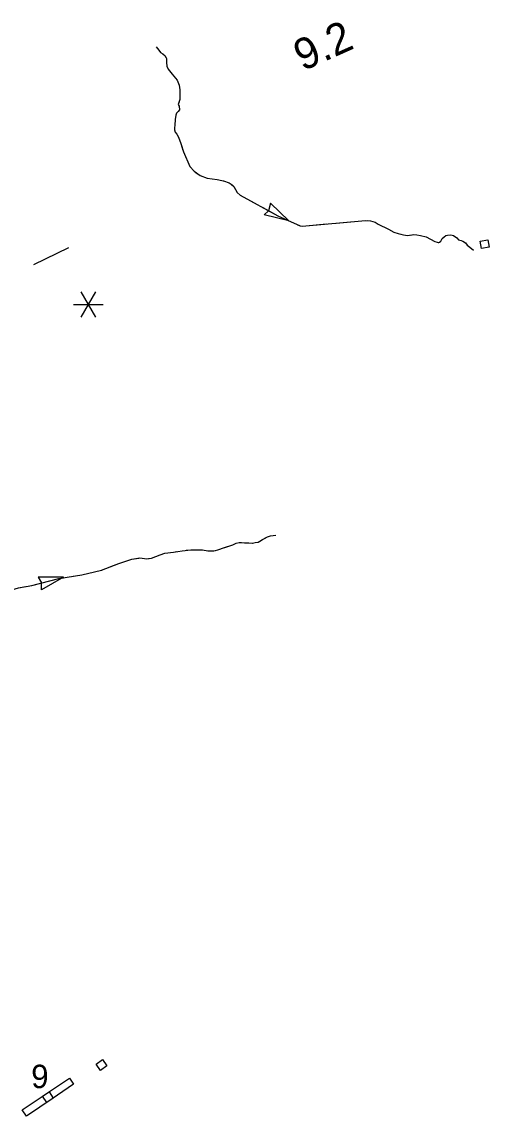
# Model space of a CAD drawing. Extents: x -160 to 6143532, y -375 to 762199.
# Drawn here: x -87.11 to -74.02, y -269.5 to -238.84 of the extents above; entities that cross this region are included whole.
import ezdxf

# ---------------------------------------------------------------- set-up
doc = ezdxf.new("R2010")
doc.units = 0
for name, color, linetype in [('Level 43', 7, 'Continuous'), ('Level 48', 7, 'Continuous'), ('Level 56', 7, 'Continuous')]:
    doc.layers.add(name, color=color, linetype=linetype)

msp = doc.modelspace()

# ---------------------------------------------------------------- linework, layer by layer
at = {"layer": 'Level 43'}
for p, q in [((-80.144, -243.926), (-80.2, -244.136)), ((-79.632, -244.418), (-80.144, -243.926)), ((-80.322, -244.248), (-80.2, -244.136)), ((-79.632, -244.418), (-80.322, -244.248)), ((-85.945, -254.403), (-86.655, -254.4)), ((-86.655, -254.4), (-86.561, -254.564)), ((-85.945, -254.403), (-86.561, -254.755)), ((-86.561, -254.755), (-86.56, -254.566))]:
    msp.add_line(p, q, dxfattribs=at)
for points in [[(-83.343, -239.541), (-83.273, -239.64), (-83.23, -239.703), (-83.162, -239.742), (-83.099, -239.795), (-83.06, -239.868), (-83.06, -239.98), (-83.05, -240.087), (-83.011, -240.169), (-82.895, -240.305), (-82.763, -240.48), (-82.7, -240.621), (-82.681, -240.752), (-82.686, -241.02), (-82.729, -241.16), (-82.7, -241.209), (-82.695, -241.311), (-82.734, -241.355), (-82.778, -241.403), (-82.797, -241.462), (-82.812, -241.578), (-82.822, -241.734), (-82.831, -241.812), (-82.831, -241.87), (-82.812, -241.938), (-82.768, -241.991), (-82.725, -242.079), (-82.657, -242.249), (-82.584, -242.487), (-82.399, -242.897), (-82.283, -243.028), (-82.118, -243.149), (-81.914, -243.227), (-81.637, -243.256), (-81.457, -243.3), (-81.302, -243.358), (-81.243, -243.392), (-81.17, -243.46), (-81.082, -243.626), (-80.994, -243.698), (-79.935, -244.282), (-79.309, -244.563), (-79.241, -244.568), (-79.149, -244.558), (-77.585, -244.418), (-77.438, -244.411), (-77.341, -244.421), (-77.273, -244.436), (-77.21, -244.455), (-77.123, -244.513), (-76.841, -244.649), (-76.691, -244.732), (-76.569, -244.771), (-76.414, -244.81), (-76.307, -244.829), (-76.127, -244.805), (-76.045, -244.815), (-75.938, -244.829), (-75.777, -244.868), (-75.539, -244.994), (-75.471, -245.019), (-75.446, -245.022), (-75.427, -245.022), (-75.407, -245.017), (-75.373, -244.988), (-75.332, -244.918), (-75.281, -244.864), (-75.235, -244.833), (-75.181, -244.818), (-75.087, -244.813), (-75.016, -244.828), (-74.924, -244.891), (-74.878, -244.947), (-74.802, -244.969), (-74.756, -244.991), (-74.681, -245.039), (-74.635, -245.102), (-74.557, -245.156), (-74.457, -245.236)], [(-83.343, -239.541), (-83.273, -239.64), (-83.23, -239.703), (-83.162, -239.742), (-83.099, -239.795), (-83.075, -239.84)], [(-83.041, -240.106), (-83.011, -240.169), (-82.895, -240.305), (-82.763, -240.48), (-82.7, -240.621), (-82.681, -240.752), (-82.682, -240.817)], [(-82.707, -241.087), (-82.729, -241.16), (-82.7, -241.209), (-82.695, -241.311), (-82.734, -241.355), (-82.778, -241.403), (-82.797, -241.462), (-82.812, -241.578), (-82.822, -241.734), (-82.831, -241.812), (-82.831, -241.858)], [(-82.716, -242.101), (-82.657, -242.249), (-82.598, -242.44)], [(-82.235, -243.063), (-82.118, -243.149), (-81.914, -243.227), (-81.637, -243.256), (-81.465, -243.298)], [(-81.221, -243.413), (-81.17, -243.46), (-81.082, -243.626), (-80.994, -243.698), (-80.601, -243.915)], [(-80.362, -244.047), (-80.003, -244.244)], [(-80.003, -244.244), (-79.935, -244.282), (-79.632, -244.418)], [(-79.383, -244.53), (-79.309, -244.563), (-79.241, -244.568), (-79.149, -244.558), (-78.574, -244.507)], [(-78.302, -244.482), (-77.585, -244.418), (-77.486, -244.413)], [(-77.218, -244.453), (-77.21, -244.455), (-77.123, -244.513), (-76.841, -244.649), (-76.691, -244.732), (-76.569, -244.771), (-76.478, -244.794)], [(-76.21, -244.816), (-76.127, -244.805), (-76.045, -244.815), (-75.938, -244.829), (-75.777, -244.868), (-75.539, -244.994), (-75.471, -245.019), (-75.446, -245.022), (-75.433, -245.022)], [(-75.243, -244.838), (-75.235, -244.833), (-75.181, -244.818), (-75.087, -244.813), (-75.016, -244.828), (-74.924, -244.891), (-74.878, -244.947), (-74.802, -244.969), (-74.756, -244.991), (-74.681, -245.039), (-74.635, -245.102), (-74.557, -245.156), (-74.549, -245.163)], [(-87.209, -254.704), (-86.835, -254.637), (-86.078, -254.438), (-85.428, -254.338), (-84.879, -254.205), (-84.397, -254.022), (-84.031, -253.897), (-83.807, -253.864), (-83.609, -253.887), (-83.476, -253.866), (-83.231, -253.779), (-83.102, -253.733), (-82.861, -253.7), (-82.62, -253.662), (-82.371, -253.633), (-82.201, -253.633), (-82.047, -253.633), (-81.901, -253.662), (-81.827, -253.662), (-81.735, -253.662), (-81.623, -253.638), (-81.428, -253.575), (-81.203, -253.492), (-81.104, -253.45), (-81.025, -253.43), (-80.958, -253.43), (-80.871, -253.442), (-80.754, -253.442), (-80.651, -253.45), (-80.572, -253.434), (-80.488, -253.417), (-80.397, -253.363), (-80.23, -253.276), (-80.146, -253.243), (-80.072, -253.238), (-79.993, -253.226)], [(-80.382, -253.355), (-80.23, -253.276), (-80.146, -253.243), (-80.072, -253.238), (-79.993, -253.226)], [(-81.427, -253.575), (-81.203, -253.492), (-81.104, -253.45), (-81.025, -253.43), (-80.958, -253.43), (-80.871, -253.442), (-80.754, -253.442), (-80.651, -253.45), (-80.635, -253.447)], [(-83.565, -253.88), (-83.476, -253.866), (-83.231, -253.779), (-83.102, -253.733), (-82.861, -253.7), (-82.773, -253.686)], [(-82.503, -253.649), (-82.371, -253.633), (-82.201, -253.633), (-82.047, -253.633), (-81.901, -253.662), (-81.827, -253.662), (-81.735, -253.662), (-81.689, -253.652)], [(-84.617, -254.106), (-84.397, -254.022), (-84.031, -253.897), (-83.836, -253.868)], [(-86.737, -254.612), (-86.078, -254.438), (-85.942, -254.417)], [(-85.672, -254.376), (-85.428, -254.338), (-85.27, -254.3)], [(-85.27, -254.3), (-84.879, -254.205), (-84.872, -254.202)], [(-87.786, -254.904), (-87.508, -254.795), (-87.209, -254.704), (-87.004, -254.668)]]:
    msp.add_lwpolyline(points, dxfattribs=at)
at = {"layer": 'Level 48'}
for p, q in [((-85.043, -246.405), (-85.456, -247.121)), ((-85.456, -246.405), (-85.043, -247.121)), ((-85.663, -246.763), (-84.836, -246.763))]:
    msp.add_line(p, q, dxfattribs=at)
at = {"layer": 'Level 56'}
for points in [[(-74.058, -244.947), (-74.018, -245.158), (-74.23, -245.198), (-74.27, -244.987)], [(-84.731, -268.097), (-84.908, -268.22), (-85.031, -268.042), (-84.853, -267.92)], [(-86.412, -269.117), (-86.528, -268.945), (-85.777, -268.44), (-85.662, -268.611)], [(-86.984, -269.502), (-87.1, -269.33), (-86.349, -268.825), (-86.234, -268.996)]]:
    msp.add_lwpolyline(points, close=True, dxfattribs=at)
msp.add_lwpolyline([(-86.776, -245.644), (-85.796, -245.169)], dxfattribs=at)

# ---------------------------------------------------------------- texts
at = {"layer": 'Level 48'}
msp.add_text('9.2', height=0.8737, rotation=24.1364, dxfattribs=at).set_placement((-79.24, -240.235))
at = {"layer": 'Level 56'}
msp.add_text('9', height=0.655, dxfattribs=at).set_placement((-86.848, -268.717))

doc.saveas('drawing.dxf')
